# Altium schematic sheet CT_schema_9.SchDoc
size 277 x 170 mm
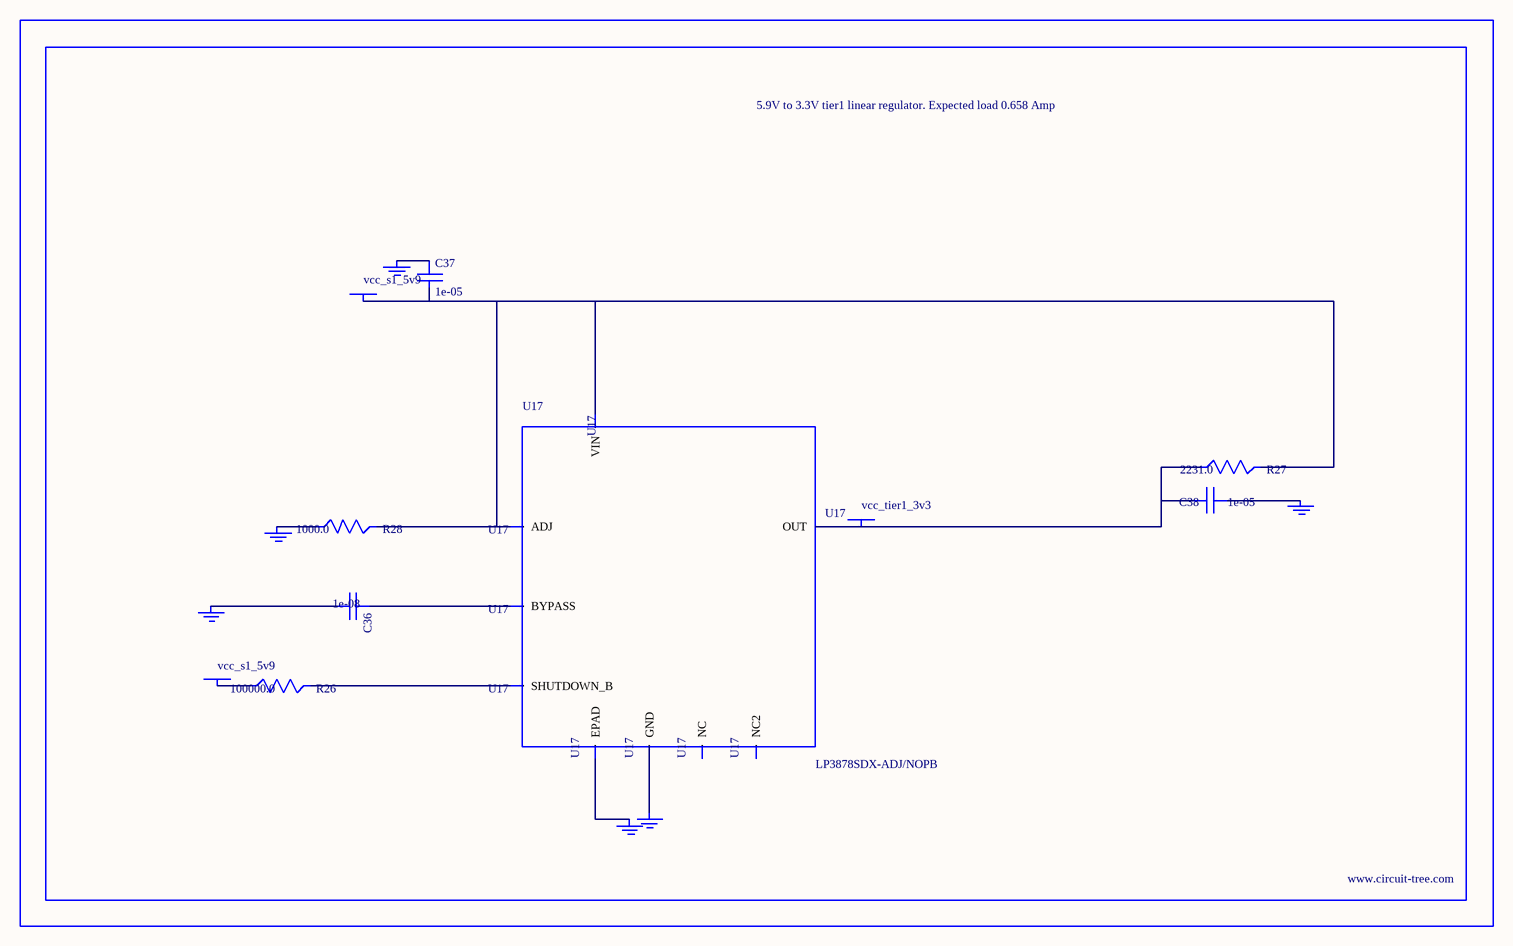
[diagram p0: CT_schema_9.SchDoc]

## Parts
BORDER8  (no value)
C36  1e-08  [C0402]
C37  1e-05  [C1206]
C38  1e-05  [C1210]
GND_INSTANCE_8_0  (no value)
GND_INSTANCE_8_1  (no value)
GND_INSTANCE_8_2  (no value)
GND_INSTANCE_8_3  (no value)
GND_INSTANCE_8_4  (no value)
GND_INSTANCE_8_5  (no value)
POWER_INSTANCE_8_0  vcc_s1_5v9
POWER_INSTANCE_8_1  vcc_s1_5v9
POWER_INSTANCE_8_2  vcc_tier1_3v3
R26  100000.0  [R0603]
R27  2231.0  [R0603]
R28  1000.0  [R0603]
U17  LP3878SDX-ADJ/NOPB  [WSON-8]

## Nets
NetC36_1: C36.1 U17.1(BYPASS)
NetC36_2: C36.2 GND_INSTANCE_8_0.0(GND)
NetC37_1: C37.1 GND_INSTANCE_8_1.0(GND)
NetC37_2: C37.2 POWER_INSTANCE_8_0.0(PWR) R27.2 R28.2 U17.4(VIN) U17.6(ADJ)
NetC38_1: C38.1 GND_INSTANCE_8_2.0(GND)
NetC38_2: C38.2 POWER_INSTANCE_8_2.0(PWR) R27.1 U17.5(OUT)
NetGND_INSTANCE_8_3_0: GND_INSTANCE_8_3.0(GND) R28.1
NetGND_INSTANCE_8_4_0: GND_INSTANCE_8_4.0(GND) U17.PAD(EPAD)
NetGND_INSTANCE_8_5_0: GND_INSTANCE_8_5.0(GND) U17.3(GND)
NetPOWER_INSTANCE_8_1_0: POWER_INSTANCE_8_1.0(PWR) R26.1
NetR26_2: R26.2 U17.8(SHUTDOWN_B)

Not connected (* = marked no-connect by the designer): U17 2(NC) 7(NC2)

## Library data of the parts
BORDER8 = BORDER_PAGE8
C36 = C0402C103K3RAC
C37 = C1206C106K3RACTU
C38 = GRM32DR61E106MA12L
GND_INSTANCE_8_0-GND_INSTANCE_8_5 = GND
POWER_INSTANCE_8_0-POWER_INSTANCE_8_2 = PWR
R26 = RC0603JR-07100KL
R27 = R27
R28 = RC0603JR-071KL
